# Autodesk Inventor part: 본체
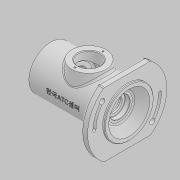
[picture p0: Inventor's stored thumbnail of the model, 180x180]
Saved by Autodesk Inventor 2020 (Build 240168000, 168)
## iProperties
Created: 2022-05
Part Number: 본체
Material: 일반
Document SubType Name: Modeling
Designer: User
Density: 1 g/cm^3
Appearance: 기본값
Mass: 255.263 g
Surface Area: 620.805 cm^2
Volume: 255.263 cm^3
Author: User
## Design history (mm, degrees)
sketch "스케치1"
  geometry: L1 (0, 0)-(0, 32); L2 (0, 32)-(102, 32); L3 (102, 32)-(102, 58); L4 (102, 58)-(112, 58); L5 (112, 58)-(112, 36); L6 (112, 36)-(115, 36); L7 (115, 36)-(115, 0); L8 (115, 0)-(0, 0); L9 (8, 0)-(8, 24); L10 (8, 24)-(11, 24); L11 (11, 24)-(11, 22.5); L12 (11, 22.5)-(22, 22.5); L13 (22, 22.5)-(22, 17.5); L14 (22, 17.5)-(24.25, 17.5); L15 (24.25, 17.5)-(24.25, 18.5); L16 (24.25, 18.5)-(26, 18.5); L17 (26, 18.5)-(26, 17.5); L18 (26, 17.5)-(37, 17.5); L19 (37, 17.5)-(37, 27); L20 (37, 27)-(75, 27); L21 (75, 27)-(75, 17.5); L22 (75, 17.5)-(86, 17.5); L23 (86, 17.5)-(86, 15); L24 (86, 15)-(91, 15); L25 (91, 15)-(91, 11); L26 (91, 11)-(93.7, 11); L27 (93.7, 11)-(93.7, 15); L28 (93.7, 15)-(101, 15); L29 (101, 15)-(101, 20); L30 (101, 20)-(115, 30)
  constraints: 60 end point, 24 perpendicular, 8 point on line, 2 vertical
  dimensions: "d22" = 102 distance of L1.end L2.end; "d23" = 13 distance between parallel lines of L7 L3; "d24" = 3 distance of L5.end L6.end; "d25" = 64 diameter of L2 L8; "d26" = 72 diameter of L6 L8; "d27" = 116 diameter of L4 L8; "d28" = 48 diameter of L10 L8; "d29" = 45 diameter of L12 L8; "d30" = 37 diameter of L16 L8; "d31" = 35 diameter of L14 L8; "d32" = 54 diameter of L20 L8; "d33" = 22 diameter of L26 L8; "d34" = 60 diameter of L30.end L8; "d35" = 40 diameter of L29.end L8; "d36" = 30 diameter of L28 L8; "d37" = 14 horizontal distance of L30.end L29.end; "d39" = 5 distance of L23.end L24.end; "d40" = 29 distance between parallel lines of L7 L23; "d41" = 11 distance of L21.end L22.end; "d42" = 38 distance of L19.end L20.end; "d43" = 11 distance of L17.end L18.end; "d44" = 7.3 distance of L27.end L28.end; "d45" = 1.75 distance of L15.end L16.end; "d46" = 4 distance between parallel lines of L13 L17; "d47" = 3 distance of L9.end L10.end; "d48" = 8 distance between parallel lines of L9 L1
revolve "회전1" sketch "스케치1" stored, may be unused: angle "d49" = 90 deg
sketch "스케치2"
  geometry: L1 (-33.985, 47)-(33.985, 47); L2 (-33.985, -47)-(33.985, -47); A1 r 58 centre (0, 0) between (-33.985, 47) and (33.985, 47) reference; 1 further point
  constraints: 4 end point, 4 point on circle, 1 horizontal, 1 parallel, 1 vertical alignment
  dimensions: "d50" = 94 distance between parallel lines of L2 L1
extrude "돌출1" cut sketch "스케치2" distance "d51" = 10; taper "d52" = 0 deg
sketch "스케치4"
  geometry: L1 (0, 0)-(48, 0); L2 (0, 0)-(36.77, 30.854); L3 (0, 0)-(-36.77, -30.854); L4 (0, 0)-(-48, 0); A1 r 48 centre (0, 0) between (48, 0) and (36.77, 30.854); A2 r 52 centre (0, 0) between (52, 0) and (39.834, 33.425); A3 r 44 centre (0, 0) between (44, 0) and (33.706, 28.283); A4 r 4 centre (48, 0) between (44, 0) and (52, 0); A5 r 4 centre (36.77, 30.854) between (39.834, 33.425) and (33.706, 28.283); A6 r 48 centre (0, 0) between (-48, 0) and (-36.77, -30.854); A7 r 52 centre (0, 0) between (-52, 0) and (-39.834, -33.425); A8 r 44 centre (0, 0) between (-44, 0) and (-33.706, -28.283); A9 r 4 centre (-48, 0) between (-44, 0) and (-52, 0); A10 r 4 centre (-36.77, -30.854) between (-39.834, -33.425) and (-33.706, -28.283); A11 r 50.25 centre (0, 0) between (50.25, 0) and (38.494, 32.3); A12 r 2.25 centre (48, 0) between (45.75, 0) and (50.25, 0); A13 r 45.75 centre (0, 0) between (45.75, 0) and (35.047, 29.408); A14 r 2.25 centre (36.77, 30.854) between (38.494, 32.3) and (35.047, 29.408); A15 r 45.75 centre (0, 0) between (-45.75, 0) and (-35.047, -29.408); A16 r 2.25 centre (-48, 0) between (-45.75, 0) and (-50.25, 0); A17 r 50.25 centre (0, 0) between (-50.25, 0) and (-38.494, -32.3); A18 r 2.25 centre (-36.77, -30.854) between (-38.494, -32.3) and (-35.047, -29.408); 1 further point
  constraints: 36 point on circle, 18 centre point, 8 end point, 8 tangent, 2 coincident, 2 horizontal alignment, 6 other
  dimensions: "d62" = 48 radius of A1; "d63" = 40 deg angle of L1 L2; "d64" = 48 radius of A6; "d65" = 40 deg angle of L4 L3; "d66" = 4 radius of A5; "d67" = 4 radius of A10; "d68" = 4.5 distance of A11.end A13.end; "d69" = 4.5 distance of A15.end A17.end
extrude "돌출2" cut sketch "스케치4" extent not by distance; stored distance "d70" = 0; taper "d71" = 0 deg
extrude "돌출3" cut sketch "스케치4" distance "d72" = 4.4; taper "d73" = 0 deg
sketch "스케치5"
  geometry: C1 r 4 at (36.77, 30.854); C2 r 4 at (-36.77, -30.854); A1 r 2.25 centre (36.77, 30.854) between (38.494, 32.3) and (35.047, 29.408) reference; A2 r 2.25 centre (-36.77, -30.854) between (-38.494, -32.3) and (-35.047, -29.408) reference; 1 further point
  constraints: 2 centre point, 2 coincident
  dimensions: "d74" = 8 diameter of C1; "d75" = 8 diameter of C2
extrude "돌출4" cut sketch "스케치5" extent not by distance; stored distance "d76" = 102; taper "d77" = 0 deg
node "작업 평면1"
sketch "스케치6"
  geometry: L1 (0, 32)-(0, -32) reference; C1 r 25 at (-56, 0); 2 further points
  constraints: 1 centre point, 1 horizontal alignment, 1 midpoint
  dimensions: "d79" = 50 diameter of C1; "d80" = 56 distance from line of C1.centre L1
extrude "돌출5" join sketch "스케치6" stored distance "d81" = 4.4; taper "d82" = 5 deg
sketch "스케치7"
  geometry: C1 r 25 at (0, 0) reference; 2 further points
  constraints: 1 coincident
hole "구멍1" sketch "스케치7" at (0, 0) diameter "d83" = 32; stored, may be unused: countersink angle "d87" = 90 deg, drill point angle "d89" = 118 deg; dims "d84" = 8, "d85" = 4, "d86" = 2, "d88" = 40
sketch "스케치8"
  geometry: L1 (0, 0)-(0, 20.5); C1 r 16 at (0, 0) reference; 2 further points
  constraints: 2 end point, 1 coincident, 1 vertical
  dimensions: "d90" = 20.5 distance of L1.start L1.end
hole "구멍2" sketch "스케치8" at (0, 20.5) diameter "d91" = 2.62111; stored, may be unused: countersink angle "d95" = 90 deg, drill point angle "d97" = 118 deg; dims "d92" = 6, "d93" = 4, "d94" = 2, "d96" = 8
node "작업 평면2"
sketch "스케치9"
  geometry: L1 (61, -47)-(61, 47) reference; 2 further points
  constraints: 1 horizontal alignment, 1 other
  dimensions: "d101" = 62 distance from line of point (-1, 0) L1
feature "엠보싱1" sketch "스케치9" dims "d22" = 102, "d23" = 13, "d24" = 3, "d25" = 64, "d26" = 72, "d27" = 116, "d28" = 48, "d29" = 45, "d30" = 37, "d31" = 35, "d32" = 54, "d33" = 22, "d34" = 60, "d35" = 40, "d36" = 30, "d37" = 14, "d39" = 5, "d40" = 29, "d41" = 11, "d42" = 38, "d43" = 11, "d44" = 7.3, "d45" = 1.75, "d46" = 4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
fillet "모깎기1" dims "d104" = 0.5, "d105" = 0.6
chamfer "모따기1" distance "d106" = 0.7; stored, may be unused: second distance "d107" = 2, angle "d108" = 30 deg
fillet "모깎기2" dims "d109" = 3
chamfer "모따기2" distance "d110" = 1; stored, may be unused: second distance "d111" = 2, angle "d112" = 30 deg
sketch "스케치10"
  geometry: C1 r 32 at (0, 0) reference; 2 further points
  constraints: 1 coincident
hole "구멍3" sketch "스케치10" at (0, 0) diameter "d113" = 43.376; stored, may be unused: countersink angle "d117" = 90 deg, drill point angle "d119" = 118 deg; dims "d114" = 90, "d115" = 4, "d116" = 2, "d118" = 8
fillet "모깎기3" dims "d120" = 3
fillet "모깎기4" dims "d124" = 3
chamfer "모따기4" distance "d125" = 1; stored, may be unused: second distance "d126" = 2, angle "d127" = 30 deg
node "솔리드1"
pattern_circular "원형 패턴1" dims angle "d99" = 360 deg
feature "A9D066F2-1C7D-4E18-AEED-F7BC21143FA4" dims "d83" = 32, "d84" = 8, "d85" = 4, "d86" = 2, "d87" = 90 deg, "d88" = 40, "d89" = 118 deg
other parameters: "d78" = 38
